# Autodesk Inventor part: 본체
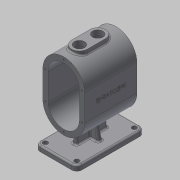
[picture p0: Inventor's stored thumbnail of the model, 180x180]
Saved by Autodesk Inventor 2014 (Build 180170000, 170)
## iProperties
Created: 2016-12
Part Number: 본체
Material: 일반
Document SubType Name: Modeling
Designer: mduedu
Density: 1 g/cm^3
Mass: 432.112 g
Surface Area: 1014.94 cm^2
Volume: 432.112 cm^3
Appearance: 기본값
Author: mduedu
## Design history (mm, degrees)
sketch "스케치1"
  geometry: L1 (40, -25)-(40, 25); L2 (-40, 25)-(-40, -25); L3 (-40, -25)-(40, 25); L4 (40, -25)-(-40, 25); L5 (0, 25)-(0, -25); A1 r 40 centre (0, 25) between (40, 25) and (-40, 25); A2 r 40 centre (0, -25) between (-40, -25) and (40, -25); 1 further point
  constraints: 10 end point, 4 point on circle, 3 tangent, 2 centre point, 2 midpoint, 2 parallel, 1 vertical
  dimensions: "d0" = 130 dimension on A2 A1; "d2" = 80 distance between parallel lines of L1 L2
extrude "돌출1" new body sketch "스케치1" stored distance "d3" = 100; taper "d4" = 0 deg
feature "쉘1" dims "d5" = 10
sketch "스케치2"
  geometry: L1 (-90, 65)-(-100, 65); L2 (-100, 65)-(-100, -65); L3 (-100, -65)-(-90, -65); L4 (-90, -65)-(-90, 65); 2 further points
  constraints: 8 end point, 2 parallel, 1 horizontal, 1 horizontal alignment, 1 midpoint, 1 perpendicular
  dimensions: "d6" = 100 distance from line of L2 point (0, 0); "d7" = 130 distance of L1.end L2.end; "d8" = 10 distance of L2.end L3.end
extrude "돌출2" join sketch "스케치2" stored distance "d9" = 80; taper "d10" = 0 deg
fillet "모깎기1" dims "d11" = 10
sketch "스케치3"
  geometry: L1 (-10, 10)-(-10, 120) reference; L2 (60, 0)-(0, 0) reference; L3 (70, 120)-(70, 10) reference; L4 (0, 130)-(60, 130) reference; A1 r 10 centre (0, 120) between (0, 130) and (-10, 120) reference; A2 r 10 centre (0, 10) between (-10, 10) and (0, 0) reference; A3 r 10 centre (60, 10) between (60, 0) and (70, 10) reference; A4 r 10 centre (60, 120) between (70, 120) and (60, 130) reference; 5 further points
  constraints: 4 coincident
hole "구멍1" sketch "스케치3" at (60, 120), (60, 10), (0, 10), (0, 120) diameter "d12" = 9; stored, may be unused: countersink angle "d16" = 90 deg, drill point angle "d18" = 118 deg; dims "d13" = 6, "d14" = 4, "d15" = 2, "d17" = 8
sketch "스케치5"
  geometry: L1 (34, 35)-(26, 35); L2 (26, 35)-(26, 95); L3 (26, 95)-(34, 95); L4 (34, 95)-(34, 35); L5 (34, 35)-(26, 95); L6 (26, 35)-(34, 95); 1 further point
  constraints: 12 end point, 2 midpoint, 2 parallel, 1 horizontal, 1 perpendicular
  dimensions: "d22" = 8 distance of L2.end L3.end; "d24" = 60 distance of L1.end L2.end
extrude "돌출3" join sketch "스케치5" stored distance "d25" = 80; taper "d26" = 0 deg
feature "면 기울기1" dims angle "d27" = 5 deg
sketch "스케치6"
  geometry: L1 (-30, -90)-(30, -90) reference; L2 (-15.072, -62.052)-(-20, -90); A1 r 40 centre (0, -25) between (-40, -25) and (40, -25) reference; 1 further point
  constraints: 2 end point, 1 point on circle, 1 point on line
  dimensions: "d28" = 20 horizontal distance of A1.centre L2.end; "d29" = 80 deg angle of L2 L1
feature "리브1" sketch "스케치6" dims "d30" = 1, "d31" = 8, "d32" = 0, "d33" = 0, "d34" = 1, "d35" = 1
fillet "모깎기2" dims "d36" = 3
fillet "모깎기3" dims "d37" = 3, "d38" = 3
node "작업 평면1"
sketch "스케치9"
  geometry: 1 further point
sketch "스케치7"
  geometry: L1 (40, 50)-(-40, 50) reference; C1 r 15 at (0, 20); 1 further point
  constraints: 1 centre point, 1 vertical alignment
  dimensions: "d40" = 30 diameter of C1; "d41" = 30 distance from line of C1.centre L1
extrude "돌출4" join sketch "스케치7" stored distance "d42" = 80; taper "d43" = 0 deg
sketch "스케치15"
  geometry: C1 r 15 at (0, -15); C2 r 15 at (0, 20) reference; 1 further point
  constraints: 1 centre point, 1 vertical alignment
  dimensions: "d83" = 30 diameter of C1; "d84" = 35 distance of C1.centre C2.centre
extrude "돌출6" join sketch "스케치15" stored distance "d85" = 10; taper "d86" = 0 deg
hole "구멍2" diameter "d46" = 20; stored, may be unused: countersink angle "d50" = 90 deg, drill point angle "d52" = 118 deg; dims "d44" = 10, "d45" = 10, "d47" = 6, "d48" = 4, "d49" = 2, "d51" = 8
hole "구멍6" diameter "d89" = 20; stored, may be unused: countersink angle "d93" = 90 deg, drill point angle "d95" = 118 deg; dims "d87" = 10, "d88" = 10, "d90" = 6, "d91" = 4, "d92" = 2, "d94" = 8
node "작업 평면2"
sketch "스케치8"
  geometry: C1 r 15 at (0, 0) reference; C2 r 15 at (0, 0); 1 further point
  constraints: 1 centre point, 1 coincident
  dimensions: "d55" = 30 diameter of C2
extrude "돌출5" cut sketch "스케치8" stored distance "d56" = 80; taper "d57" = 0 deg
sketch "스케치16"
  geometry: C1 r 15 at (0, 35); 2 further points
  constraints: 1 centre point, 1 coincident, 1 vertical alignment
  dimensions: "d96" = 30 diameter of C1
extrude "돌출7" cut sketch "스케치16" stored distance "d97" = 10; taper "d98" = 0 deg
sketch "스케치17"
  geometry: L1 (15, 0)-(15, -35); L2 (-15, 0)-(-15, -35); C1 r 10 at (0, 0) reference; C2 r 10 at (0, -35) reference; A1 r 15 centre (0, 0) between (15, 0) and (-15, 0) reference; A2 r 15 centre (0, -35) between (15, -35) and (-15, -35) reference; 1 further point
  constraints: 4 end point, 4 point on circle, 3 tangent, 1 vertical
extrude "돌출8" join sketch "스케치17" stored distance "d99" = 10; taper "d100" = 0 deg
fillet "모깎기5" dims "d101" = 3
chamfer "모따기1" distance "d58" = 1; stored, may be unused: second distance "d59" = 2, angle "d60" = 45 deg
sketch "스케치10"
  geometry: 2 further points
  constraints: 1 coincident, 1 other
feature "엠보싱1" sketch "스케치10" dims "d0" = 130, "d2" = 80, "d11" = 10, "d61" = 0.5, "d62" = 0
sketch "스케치11"
  geometry: 1 further point
hole "구멍3" sketch "스케치11" at (0, 60) diameter "d63" = 3.242; stored, may be unused: countersink angle "d67" = 90 deg, drill point angle "d69" = 120 deg; dims "d64" = 8.6, "d65" = 4, "d66" = 2, "d68" = 10.6
sketch "스케치12"
  geometry: 1 further point
hole "구멍5" sketch "스케치12" at (0, 60) diameter "d70" = 3.242; stored, may be unused: countersink angle "d74" = 90 deg, drill point angle "d76" = 120 deg; dims "d71" = 8.6, "d72" = 4, "d73" = 2, "d75" = 10.6
node "솔리드1"
mirror "대칭1"
pattern_linear "직사각형 패턴1"
pattern_linear "직사각형 패턴2"
node "투영된 루프1"
sketch "스케치13"
  geometry: L1 (-40, 25)-(-40, -25) reference; L2 (40, -25)-(40, 25) reference; L3 (35, 25)-(35, -25); L4 (-35, -25)-(-35, 25); A1 r 40 centre (0, 25) between (40, 25) and (-40, 25) reference; A2 r 40 centre (0, -25) between (-40, -25) and (40, -25) reference; A3 r 35 centre (0, 25) between (35, 25) and (-35, 25); A4 r 35 centre (0, -25) between (-35, -25) and (35, -25); 2 further points
  constraints: 5 point on circle, 4 end point, 2 centre point, 3 other
  dimensions: "d77" = 5 distance between parallel lines of L3 L2
sketch "스케치14"
  geometry: L1 (-40, 25)-(-40, -25) reference; L2 (40, -25)-(40, 25) reference; L3 (35, 25)-(35, -25); L4 (-35, -25)-(-35, 25); A1 r 40 centre (0, 25) between (40, 25) and (-40, 25) reference; A2 r 40 centre (0, -25) between (-40, -25) and (40, -25) reference; A3 r 35 centre (0, 25) between (35, 25) and (-35, 25); A4 r 35 centre (0, -25) between (-35, -25) and (35, -25); 2 further points
  constraints: 5 point on circle, 4 end point, 2 centre point, 3 other
  dimensions: "d80" = 5 distance between parallel lines of L2 L3
node "투영된 루프3"
node "투영된 루프4"
node "투영된 루프5"
